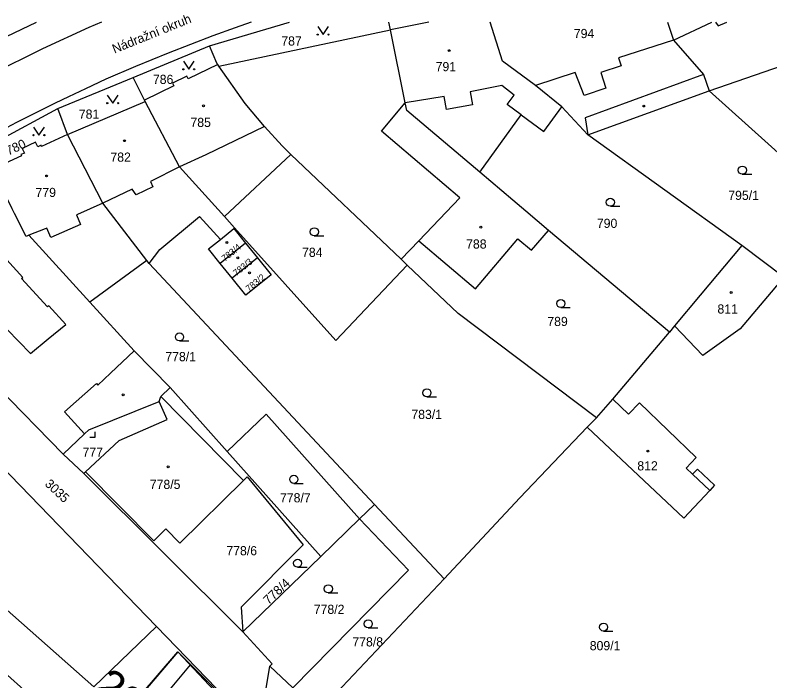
# Model space of a CAD drawing. Extents: x -496682 to -495776, y -1088797 to -1088018.
# Drawn here: x -496499.5 to -496359.5, y -1088141.5 to -1088018.2 of the extents above; entities that cross this region are included whole.
import ezdxf

# ---------------------------------------------------------------- set-up
doc = ezdxf.new("R2010")
doc.units = 0
for name, color, linetype in [('Hranice parcel', 7, 'Continuous'), ('Parcelní čísla', 7, 'Continuous'), ('Pop  PČ popisy', 7, 'Continuous'), ('Vnitřní kresba', 7, 'Continuous'), ('Vrstva 20', 7, 'Continuous'), ('Vrstva 54', 7, 'Continuous'), ('Vrstva 7', 7, 'Continuous'), ('Značky budov', 7, 'Continuous'), ('Značky kultur', 7, 'Continuous')]:
    doc.layers.add(name, color=color, linetype=linetype)

msp = doc.modelspace()

# ---------------------------------------------------------------- linework, layer by layer
at = {"layer": 'Hranice parcel'}
for p, q in [((-496463.43, -1088023.85), (-496448.62, -1088019.49)), ((-496429.86, -1088020.9), (-496430.15, -1088019.49)), ((-496461.7, -1088027.6), (-496429.86, -1088020.9)), ((-496477.56, -1088029.71), (-496463.43, -1088023.85)), ((-496461.7, -1088027.6), (-496461.89, -1088027.33)), ((-496491.56, -1088035.46), (-496477.56, -1088029.71)), ((-496475.51, -1088033.91), (-496477.56, -1088029.71)), ((-496393.29, -1088040.33), (-496370.79, -1088032.22)), ((-496370.79, -1088032.22), (-496342.08, -1088057.91)), ((-496489.76, -1088040.29), (-496475.36, -1088034.2)), ((-496475.36, -1088034.2), (-496475.51, -1088033.91)), ((-496505.64, -1088043.04), (-496491.56, -1088035.46)), ((-496489.76, -1088040.29), (-496491.56, -1088035.46)), ((-496393.29, -1088040.33), (-496398.07, -1088035.13)), ((-496364.73, -1088060.87), (-496393.29, -1088040.33)), ((-496448.33, -1088044.01), (-496460.66, -1088055.5)), ((-496427.9, -1088063.4), (-496448.33, -1088044.01)), ((-496458.78, -1088057.6), (-496460.66, -1088055.5)), ((-496461.41, -1088059.72), (-496458.93, -1088057.71)), ((-496458.93, -1088057.71), (-496458.78, -1088057.6)), ((-496458.93, -1088057.71), (-496456.73, -1088060.44)), ((-496378.15, -1088076.93), (-496400.58, -1088058.06)), ((-496456.73, -1088060.44), (-496461.42, -1088064.22)), ((-496456.73, -1088060.44), (-496454.53, -1088063.16)), ((-496356.91, -1088066.71), (-496364.73, -1088060.87)), ((-496475.05, -1088063.65), (-496485.62, -1088071.37)), ((-496474.62, -1088064.21), (-496475.05, -1088063.65)), ((-496432.83, -1088108.84), (-496474.62, -1088064.21)), ((-496459.23, -1088066.92), (-496461.42, -1088064.22)), ((-496454.53, -1088063.16), (-496459.23, -1088066.92)), ((-496426.74, -1088064.5), (-496427.9, -1088063.4)), ((-496377.22, -1088075.77), (-496378.15, -1088076.93)), ((-496388.65, -1088089.36), (-496378.15, -1088076.93)), ((-496472.42, -1088088.85), (-496470.72, -1088087.17)), ((-496470.72, -1088087.17), (-496460.13, -1088099.06)), ((-496472.74, -1088089.78), (-496472.42, -1088088.85)), ((-496472.42, -1088088.85), (-496457.09, -1088104.41)), ((-496391.63, -1088092.77), (-496388.65, -1088089.36)), ((-496393.38, -1088094.52), (-496391.63, -1088092.77)), ((-496442.81, -1088118.48), (-496460.13, -1088099.06)), ((-496490.59, -1088099.54), (-496486.76, -1088103.13)), ((-496486.76, -1088103.13), (-496486.4, -1088102.8)), ((-496486.76, -1088103.13), (-496457.27, -1088132.43)), ((-496435.61, -1088111.52), (-496432.83, -1088108.84)), ((-496432.83, -1088108.84), (-496419.93, -1088122.62)), ((-496435.61, -1088111.52), (-496442.81, -1088118.48)), ((-496442.81, -1088118.48), (-496457.27, -1088132.43)), ((-496419.93, -1088122.62), (-496443.22, -1088147.27)), ((-496473.26, -1088131.47), (-496458.59, -1088146.6)), ((-496447.95, -1088142.83), (-496452.25, -1088138.8))]:
    msp.add_line(p, q, dxfattribs=at)
for points in [[(-496483.48, -1088019.49), (-496485.82, -1088020.47), (-496494.39, -1088024.4), (-496503.94, -1088029.11), (-496514.57, -1088034.74), (-496524.1, -1088040.06), (-496538.76, -1088048.54), (-496541.46, -1088044.3)], [(-496538.04, -1088042.05), (-496516.74, -1088030.48), (-496513.69, -1088028.82), (-496502.45, -1088022.72), (-496495.5, -1088019.49)], [(-496455.71, -1088019.49), (-496458.68, -1088020.53), (-496462.8, -1088022.03), (-496471.09, -1088025.21), (-496477.17, -1088027.68), (-496482.67, -1088030.05), (-496486.45, -1088031.8), (-496489.58, -1088033.31), (-496492.04, -1088034.49), (-496499.24, -1088038.05), (-496511.35, -1088044.46), (-496516.12, -1088047.12), (-496528.03, -1088054.1), (-496529.12, -1088055.01), (-496530.21, -1088056.55)], [(-496422.76, -1088019.49), (-496429.86, -1088020.9)], [(-496398.07, -1088035.13), (-496402.96, -1088031.19), (-496409.09, -1088026.67), (-496411.38, -1088019.49)], [(-496378.48, -1088019.49), (-496377.39, -1088022.78), (-496371.82, -1088029.18), (-496370.79, -1088032.22)], [(-496413.29, -1088047.29), (-496426.84, -1088035.81), (-496427.12, -1088034.4), (-496429.86, -1088020.9)], [(-496461.89, -1088027.33), (-496462.08, -1088027.04), (-496463.43, -1088023.85)], [(-496370.79, -1088032.22), (-496353.78, -1088026.33), (-496348.1, -1088034.29)], [(-496461.89, -1088027.33), (-496467.37, -1088029.97), (-496467.6, -1088029.48), (-496470.27, -1088030.77), (-496470.03, -1088031.26), (-496475.51, -1088033.91)], [(-496448.33, -1088044.01), (-496449.92, -1088042.41), (-496453.22, -1088038.81), (-496456.83, -1088034.51), (-496461.7, -1088027.6)], [(-496460.66, -1088055.5), (-496468.99, -1088046.29), (-496475.36, -1088034.2)], [(-496413.29, -1088047.29), (-496405.62, -1088036.65), (-496401.42, -1088039.72), (-496398.07, -1088035.13)], [(-496489.76, -1088040.29), (-496494.55, -1088042.49), (-496494.62, -1088042.28), (-496495.28, -1088042.59), (-496495.68, -1088041.71), (-496498.16, -1088042.85), (-496497.76, -1088043.73), (-496498.39, -1088044.02), (-496498.3, -1088044.22), (-496503.75, -1088046.73)], [(-496475.05, -1088063.65), (-496483.23, -1088053.04), (-496489.76, -1088040.29)], [(-496485.62, -1088071.37), (-496496.9, -1088058.96), (-496497.43, -1088059.17), (-496499.6, -1088054.9), (-496500.03, -1088054.06), (-496503.75, -1088046.73)], [(-496400.58, -1088058.06), (-496404.74, -1088054.5), (-496407.19, -1088052.46), (-496413.29, -1088047.29)], [(-496474.62, -1088064.21), (-496472.61, -1088061.62), (-496465.26, -1088055.5), (-496461.41, -1088059.72)], [(-496426.74, -1088064.5), (-496440.01, -1088078.44), (-496458.78, -1088057.6)], [(-496427.9, -1088063.4), (-496424.63, -1088059.99), (-496414.08, -1088068.89), (-496406.22, -1088059.61), (-496403.7, -1088061.75), (-496400.58, -1088058.06)], [(-496461.42, -1088064.22), (-496463.62, -1088061.5), (-496461.41, -1088059.72)], [(-496529.16, -1088060.1), (-496522.91, -1088066.43), (-496519.74, -1088069.36), (-496513.72, -1088075.89), (-496502.91, -1088086.95), (-496490.59, -1088099.54)], [(-496364.73, -1088060.87), (-496372.46, -1088070.06), (-496377.22, -1088075.77)], [(-496454.53, -1088063.16), (-496452.01, -1088066.3), (-496456.69, -1088070.07), (-496459.23, -1088066.92)], [(-496539.03, -1088065.6), (-496535.97, -1088067.83), (-496531.62, -1088071.46), (-496507.63, -1088096.03), (-496473.26, -1088131.47)], [(-496391.63, -1088092.77), (-496417.3, -1088073.45), (-496426.74, -1088064.5)], [(-496356.91, -1088066.71), (-496365.03, -1088076.3), (-496371.95, -1088081.22), (-496377.22, -1088075.77)], [(-496470.72, -1088087.17), (-496477.42, -1088080.39), (-496485.62, -1088071.37)], [(-496559, -1088077.16), (-496484.87, -1088142.67), (-496473.26, -1088131.47)], [(-496449.81, -1088155.53), (-496454.1, -1088151.6), (-496460.56, -1088145.42), (-496469.27, -1088136.13), (-496476.41, -1088144.48), (-496483.29, -1088152.42), (-496496.71, -1088143.01), (-496497.27, -1088143.67), (-496509.81, -1088132.58), (-496512.72, -1088135.39), (-496534.24, -1088116.3), (-496558.95, -1088090.57), (-496566.25, -1088088.69), (-496568.44, -1088087.46), (-496570.32, -1088085.3), (-496571.02, -1088084.13)], [(-496388.65, -1088089.36), (-496385.72, -1088092.12), (-496383.67, -1088090.01), (-496373.16, -1088100.13), (-496375.06, -1088102.13), (-496373.87, -1088103.25), (-496372.96, -1088102.28), (-496369.75, -1088105.3), (-496370.66, -1088106.26), (-496375.45, -1088111.36), (-496393.38, -1088094.52)], [(-496490.59, -1088099.54), (-496486.61, -1088095.77), (-496485.8, -1088095), (-496472.74, -1088089.78)], [(-496486.4, -1088102.8), (-496480.19, -1088096.97), (-496471.27, -1088093.11), (-496472.74, -1088089.78)], [(-496460.13, -1088099.06), (-496452.93, -1088092.09), (-496435.61, -1088111.52)], [(-496419.93, -1088122.62), (-496405.88, -1088107.6), (-496393.38, -1088094.52)], [(-496486.4, -1088102.8), (-496473.77, -1088115.6), (-496471.54, -1088113.39), (-496468.92, -1088116.03), (-496457.09, -1088104.41)], [(-496457.09, -1088104.41), (-496456.42, -1088103.71), (-496446.07, -1088116.33), (-496457.55, -1088127.89), (-496457.27, -1088132.43)], [(-496447.95, -1088142.83), (-496426.52, -1088121), (-496435.61, -1088111.52)], [(-496457.27, -1088132.43), (-496451.82, -1088138.41), (-496452.25, -1088138.8)], [(-496458.59, -1088146.6), (-496452.94, -1088142.96), (-496452.25, -1088138.8)]]:
    msp.add_lwpolyline(points, dxfattribs=at)
at = {"layer": 'Vnitřní kresba'}
for p, q in [((-496377.39, -1088022.78), (-496370.29, -1088019.49)), ((-496369.61, -1088019.49), (-496369.07, -1088020.13)), ((-496369.07, -1088020.13), (-496367.46, -1088019.49)), ((-496377.39, -1088022.78), (-496387.56, -1088026.07)), ((-496387.56, -1088026.07), (-496387.06, -1088027.53)), ((-496387.06, -1088027.53), (-496390.85, -1088028.8)), ((-496395.59, -1088028.81), (-496402.96, -1088031.19)), ((-496393.92, -1088033.06), (-496395.59, -1088028.81)), ((-496371.82, -1088029.18), (-496393.79, -1088037.22)), ((-496390.85, -1088028.8), (-496389.93, -1088031.72)), ((-496409.24, -1088031.19), (-496415.09, -1088032.36)), ((-496406.9, -1088033), (-496409.24, -1088031.19)), ((-496389.93, -1088031.72), (-496393.92, -1088033.06)), ((-496419.92, -1088033.27), (-496427.12, -1088034.4)), ((-496419.49, -1088035.67), (-496419.92, -1088033.27)), ((-496415.09, -1088032.36), (-496414.65, -1088034.8)), ((-496408.25, -1088034.73), (-496406.9, -1088033)), ((-496431.53, -1088039.64), (-496427.12, -1088034.4)), ((-496414.65, -1088034.8), (-496419.49, -1088035.67)), ((-496405.62, -1088036.65), (-496408.25, -1088034.73)), ((-496393.79, -1088037.22), (-496393.29, -1088040.33)), ((-496453.22, -1088038.81), (-496464.13, -1088044.07)), ((-496417, -1088052.03), (-496431.53, -1088039.64)), ((-496464.13, -1088044.07), (-496468.99, -1088046.29)), ((-496468.99, -1088046.29), (-496474.39, -1088048.97)), ((-496473.91, -1088050.01), (-496477.03, -1088051.45)), ((-496474.39, -1088048.97), (-496473.91, -1088050.01)), ((-496477.79, -1088050.44), (-496483.23, -1088053.04)), ((-496477.03, -1088051.45), (-496477.79, -1088050.44)), ((-496417, -1088052.03), (-496424.63, -1088059.99)), ((-496483.23, -1088053.04), (-496487.92, -1088055.14)), ((-496487.92, -1088055.14), (-496488.09, -1088055.2)), ((-496488.09, -1088055.2), (-496487.32, -1088056.95)), ((-496487.32, -1088056.95), (-496492.84, -1088059.37)), ((-496493.9, -1088057.78), (-496496.9, -1088058.96)), ((-496493.6, -1088057.63), (-496493.9, -1088057.78)), ((-496492.84, -1088059.37), (-496493.6, -1088057.63)), ((-496498.27, -1088066.96), (-496498.05, -1088066.76)), ((-496493.45, -1088072.23), (-496498.27, -1088066.96)), ((-496493.23, -1088072.03), (-496493.45, -1088072.23)), ((-496490.07, -1088075.5), (-496493.23, -1088072.03)), ((-496493.33, -1088078.18), (-496490.07, -1088075.5)), ((-496481.79, -1088084.52), (-496477.42, -1088080.39)), ((-496484.13, -1088086.72), (-496481.79, -1088084.52)), ((-496490.3, -1088091.68), (-496484.41, -1088086.46)), ((-496484.41, -1088086.46), (-496484.13, -1088086.72)), ((-496486.61, -1088095.77), (-496490.3, -1088091.68)), ((-496373.87, -1088103.25), (-496370.66, -1088106.26))]:
    msp.add_line(p, q, dxfattribs=at)
for points in [[(-496506.32, -1088056.65), (-496504.65, -1088059.56), (-496498.05, -1088066.76)], [(-496513.72, -1088075.89), (-496507.5, -1088069.73), (-496496.62, -1088080.87), (-496493.33, -1088078.18)]]:
    msp.add_lwpolyline(points, dxfattribs=at)
at = {"layer": 'Vrstva 20'}
msp.add_line((-496503.34, -1088181.92), (-496466.96, -1088138.57), dxfattribs=at)
at = {"layer": 'Vrstva 54'}
msp.add_lwpolyline([(-496483.29, -1088152.42), (-496469.27, -1088136.13), (-496449.81, -1088155.53)], dxfattribs=at)
at = {"layer": 'Značky budov'}
for centre in [(-496419, -1088024.74), (-496464.53, -1088034.99), (-496382.91, -1088035.01), (-496479.19, -1088041.43), (-496493.63, -1088047.97), (-496413.11, -1088057.46), (-496460.19, -1088060.32), (-496458.2, -1088063.15), (-496456, -1088065.91), (-496366.67, -1088069.58), (-496479.44, -1088088.55), (-496382.11, -1088098.95), (-496471.08, -1088101.89)]:
    msp.add_circle(centre, 0.175, dxfattribs=at)
at = {"layer": 'Značky kultur'}
for p, q in [((-496364.62, -1088047.64), (-496362.87, -1088047.64)), ((-496389.09, -1088053.59), (-496387.34, -1088053.59)), ((-496443.99, -1088059.07), (-496442.24, -1088059.07)), ((-496398.27, -1088072.36), (-496396.52, -1088072.36)), ((-496468.99, -1088078.55), (-496467.24, -1088078.55)), ((-496423.11, -1088088.91), (-496421.36, -1088088.91)), ((-496485.6, -1088096.4), (-496484.6, -1088096.4)), ((-496484.6, -1088096.4), (-496484.6, -1088095.4)), ((-496447.79, -1088104.94), (-496446.04, -1088104.94)), ((-496447.09, -1088120.49), (-496445.34, -1088120.49)), ((-496441.39, -1088125.23), (-496439.64, -1088125.23)), ((-496433.99, -1088131.72), (-496432.24, -1088131.72)), ((-496390.35, -1088132.33), (-496388.6, -1088132.33))]:
    msp.add_line(p, q, dxfattribs=at)
for points in [[(-496443.36, -1088020.26), (-496442.36, -1088021.76), (-496441.36, -1088020.26)], [(-496468.27, -1088026.7), (-496467.27, -1088028.2), (-496466.27, -1088026.7)], [(-496482.38, -1088032.98), (-496481.38, -1088034.48), (-496480.38, -1088032.98)], [(-496496.05, -1088038.91), (-496495.05, -1088040.41), (-496494.05, -1088038.91)]]:
    msp.add_lwpolyline(points, dxfattribs=at)
for centre, radius in [((-496443.36, -1088021.76), 0.1), ((-496441.36, -1088021.76), 0.1), ((-496468.27, -1088028.2), 0.1), ((-496466.27, -1088028.2), 0.1), ((-496482.38, -1088034.48), 0.1), ((-496480.38, -1088034.48), 0.1), ((-496496.05, -1088040.41), 0.1), ((-496494.05, -1088040.41), 0.1), ((-496364.62, -1088046.89), 0.75), ((-496389.09, -1088052.84), 0.75), ((-496443.99, -1088058.32), 0.75), ((-496398.27, -1088071.61), 0.75), ((-496468.99, -1088077.8), 0.75), ((-496423.11, -1088088.16), 0.75), ((-496447.79, -1088104.19), 0.75), ((-496447.09, -1088119.74), 0.75), ((-496441.39, -1088124.48), 0.75), ((-496433.99, -1088130.97), 0.75), ((-496390.35, -1088131.58), 0.75)]:
    msp.add_circle(centre, radius, dxfattribs=at)

# ---------------------------------------------------------------- texts
at = {"layer": 'Parcelní čísla'}
for s, p in [('794', (-496395.86, -1088022.42)), ('787', (-496450.11, -1088023.8)), ('791', (-496421.49, -1088028.55)), ('786', (-496473.92, -1088030.92)), ('781', (-496487.66, -1088037.36)), ('785', (-496466.96, -1088038.89)), ('782', (-496481.8, -1088045.33)), ('779', (-496495.69, -1088051.87)), ('795/1', (-496367.22, -1088052.41)), ('790', (-496391.59, -1088057.6)), ('788', (-496415.84, -1088061.43)), ('784', (-496446.26, -1088062.97)), ('811', (-496369.23, -1088073.47)), ('789', (-496400.78, -1088075.78)), ('778/1', (-496471.62, -1088082.3)), ('783/1', (-496425.99, -1088093.01)), ('777', (-496486.96, -1088100)), ('812', (-496384.09, -1088102.54)), ('778/5', (-496474.5, -1088105.98)), ('778/7', (-496450.35, -1088108.46)), ('778/6', (-496460.3, -1088118.27)), ('778/2', (-496444.09, -1088129.13)), ('778/8', (-496436.93, -1088135.16)), ('809/1', (-496392.91, -1088135.87))]:
    msp.add_text(s, height=1.7, dxfattribs=at).set_placement(p)
for s, height, rotation, p in [('780', 1.7, 25, (-496500.72, -1088044.21)), ('783/4', 1.2, 39, (-496460.58, -1088063.9)), ('783/3', 1.2, 39, (-496458.45, -1088066.59)), ('783/2', 1.2, 39, (-496456.11, -1088069.49)), ('3035', 1.7, 317, (-496494.09, -1088105.21)), ('778/4', 1.7, 43, (-496452.49, -1088127.51))]:
    msp.add_text(s, height=height, rotation=rotation, dxfattribs=at).set_placement(p)
at = {"layer": 'Pop  PČ popisy'}
msp.add_text('Nádražní okruh', height=1.7, rotation=22, dxfattribs=at).set_placement((-496481.05, -1088025.3))
at = {"layer": 'Vrstva 7'}
msp.add_text('290,3', height=6, rotation=318.9438, dxfattribs=at).set_placement((-496485.58, -1088143.27))

doc.saveas('drawing.dxf')
